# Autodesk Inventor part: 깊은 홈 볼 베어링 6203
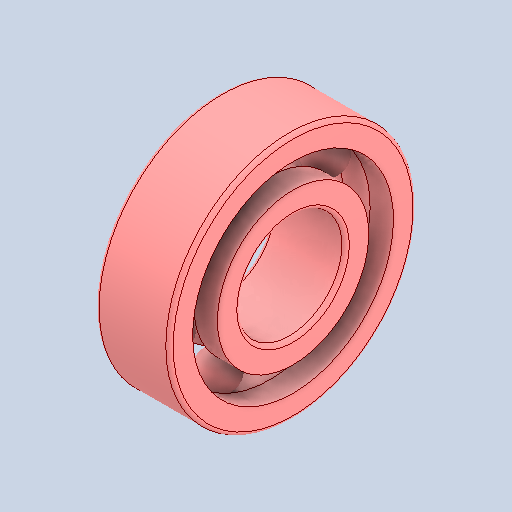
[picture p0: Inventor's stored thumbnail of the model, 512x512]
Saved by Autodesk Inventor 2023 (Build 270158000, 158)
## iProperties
Created: 2026-04
Part Number: 깊은 홈 볼 베어링 6203
Material: 강철, 연강
Description: 깊은 그루브 볼 베어링
Document SubType Name: Modeling
Designer: home
Density: 7.85 g/cm^3
Appearance: 기본값
Author: jhkim
Sending System: Autodesk Inventor 2027
Preprocessor: ST-DEVELOPER v20.1
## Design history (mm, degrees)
feature "Solid1"
feature "Solid1:1"
feature "Solid1:2"
feature "Solid1:3"
feature "Solid1:4"
feature "Solid1:5"
feature "Solid1:6"
feature "Solid1:7"
feature "Solid1:8"
node "솔리드1"
node "솔리드2"
node "솔리드3"
node "솔리드4"
node "솔리드5"
node "솔리드6"
node "솔리드7"
node "솔리드8"
node "솔리드9"
